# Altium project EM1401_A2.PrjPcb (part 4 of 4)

## Sheet FPGA.SchDoc: FPGA (optional fast AFE)
size B; Date: Not shown in title block; ApprovedBy: Not shown in title block; CheckedBy: Not shown in title block; Author: Not shown in title block; CompanyName: Not shown in title block; DrawnBy: Not shown in title block; Engineer: Not shown in title block; Organization: Not shown in title block; Address1: Not shown in title block; Address2: Not shown in title block; Address3: Not shown in title block; Address4: Not shown in title block; DocumentNumber: 1; Revision: Use project parameter SCH_Rev; SheetNumber: 3; SheetTotal: 14; PageSetup: Record=PageOptions|CenterHorizontal=True|CenterVertical=True|PrintScale=1.00|XCorrection=1.00|YCorrection=1.00|PrintKind=0|BorderSize=5000000|LeftOffset=0|BottomOffset=0|Orientation=2|PaperLength=1000|PaperWidth=1000|Scale=100|PaperSource=15|PrintQuality=600|MediaType=1|DitherType=10|PaperKind=Letter|PrintScaleMode=1
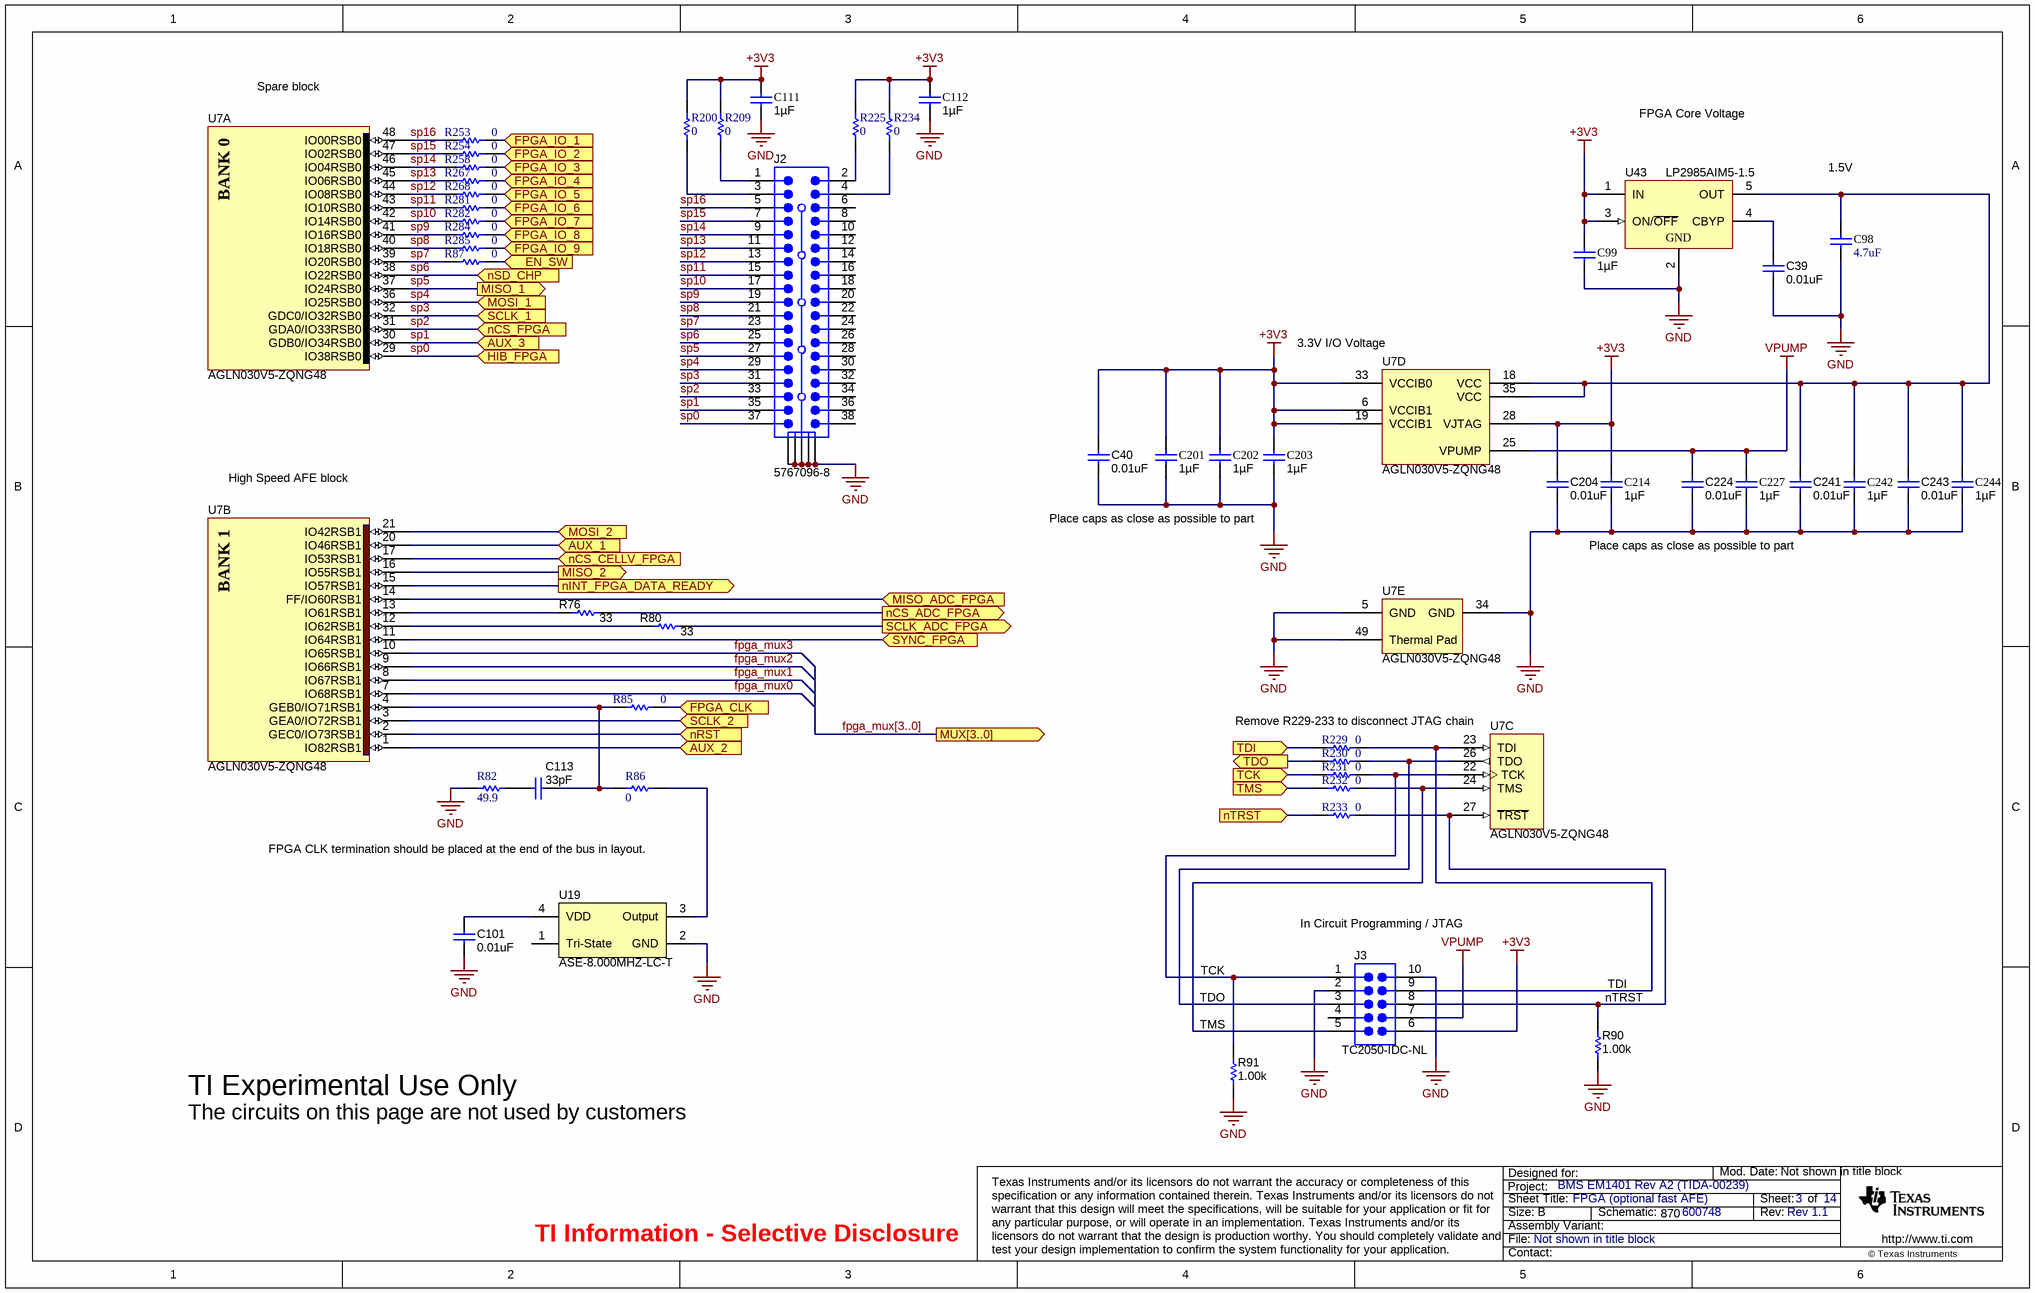
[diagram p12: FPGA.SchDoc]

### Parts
C39  value 0.01uF  [0603L]  (hidden comment: GRM188R71C103KA01D)
C40  value 0.01uF  [0603L]  (hidden comment: GRM188R71C103KA01D)
C98  value 4.7uF  [0805_HV]  (hidden comment: C0805C475K8PACTU)
C99  ValueDisplayed: 1µF  [0603L]  (hidden comment: C1608X7R1C105K)
C101  value 0.01uF  [0603L]  (hidden comment: GRM188R71C103KA01D)
C111  ValueDisplayed: 1µF  [0603L]  (hidden comment: C1608X7R1C105K)
C112  ValueDisplayed: 1µF  [0603L]  (hidden comment: C1608X7R1C105K)
C113  value 33pF  [0603L]  (hidden comment: C1608C0G1H330J)
C201  ValueDisplayed: 1µF  [0603L]  (hidden comment: C1608X7R1C105K)
C202  ValueDisplayed: 1µF  [0603L]  (hidden comment: C1608X7R1C105K)
C203  ValueDisplayed: 1µF  [0603L]  (hidden comment: C1608X7R1C105K)
C204  value 0.01uF  [0603L]  (hidden comment: GRM188R71C103KA01D)
C214  ValueDisplayed: 1µF  [0603L]  (hidden comment: C1608X7R1C105K)
C224  value 0.01uF  [0603L]  (hidden comment: GRM188R71C103KA01D)
C227  ValueDisplayed: 1µF  [0603L]  (hidden comment: C1608X7R1C105K)
C241  value 0.01uF  [0603L]  (hidden comment: GRM188R71C103KA01D)
C242  ValueDisplayed: 1µF  [0603L]  (hidden comment: C1608X7R1C105K)
C243  value 0.01uF  [0603L]  (hidden comment: GRM188R71C103KA01D)
C244  ValueDisplayed: 1µF  [0603L]  (hidden comment: C1608X7R1C105K)
J2  5767096-8  [5767096-8]
J3  TC2050-IDC-NL  [TC2050-IDC-NL-10]
R76  value 33  [0603L]  (hidden comment: CRCW060333R0JNEA)
R80  value 33  [0603L]  (hidden comment: CRCW060333R0JNEA)
R82  value 49.9  [0603L]  (hidden comment: CRCW060349R9FKEA)
R85  value 0  [0603L]  (hidden comment: CRCW06030000Z0EA)
R86  value 0  [0603L]  (hidden comment: CRCW06030000Z0EA)
R87  value 0  [0603L]  (hidden comment: CRCW06030000Z0EA)
R90  value 1.00k  [0402]  (hidden comment: CRCW04021K00FKED)
R91  value 1.00k  [0402]  (hidden comment: CRCW04021K00FKED)
R200  value 0  [0603L]  (hidden comment: CRCW06030000Z0EA)
R209  value 0  [0603L]  (hidden comment: CRCW06030000Z0EA)
R225  value 0  [0603L]  (hidden comment: CRCW06030000Z0EA)
R229  value 0  [0603L]  (hidden comment: CRCW06030000Z0EA)
R230  value 0  [0603L]  (hidden comment: CRCW06030000Z0EA)
R231  value 0  [0603L]  (hidden comment: CRCW06030000Z0EA)
R232  value 0  [0603L]  (hidden comment: CRCW06030000Z0EA)
R233  value 0  [0603L]  (hidden comment: CRCW06030000Z0EA)
R234  value 0  [0603L]  (hidden comment: CRCW06030000Z0EA)
R253  value 0  [0603L]  (hidden comment: CRCW06030000Z0EA)
R254  value 0  [0603L]  (hidden comment: CRCW06030000Z0EA)
R258  value 0  [0603L]  (hidden comment: CRCW06030000Z0EA)
R267  value 0  [0603L]  (hidden comment: CRCW06030000Z0EA)
R268  value 0  [0603L]  (hidden comment: CRCW06030000Z0EA)
R281  value 0  [0603L]  (hidden comment: CRCW06030000Z0EA)
R282  value 0  [0603L]  (hidden comment: CRCW06030000Z0EA)
R284  value 0  [0603L]  (hidden comment: CRCW06030000Z0EA)
R285  value 0  [0603L]  (hidden comment: CRCW06030000Z0EA)
U7  AGLN030V5-ZQNG48  [QN48_N]  (parts A,B,C,D,E of 5)
U19  ASE-8.000MHZ-LC-T  [ASE-xxxMHz-x-x-x]
U43  LP2985AIM5-1.5  [MF05A_N]

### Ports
AUX_1 (in), AUX_2 (in), AUX_3 (in), EN_SW (in), FPGA_CLK (in), FPGA_IO_1 (in), FPGA_IO_2 (in), FPGA_IO_3 (in), FPGA_IO_4 (in), FPGA_IO_5 (in), FPGA_IO_6 (in), FPGA_IO_7 (in), FPGA_IO_8 (in), FPGA_IO_9 (in), HIB_FPGA (in), MISO_1 (out), MISO_2 (out), MISO_ADC_FPGA (in), MOSI_1 (in), MOSI_2 (in), MUX[3..0] (out), nCS_ADC_FPGA (out), nCS_CELLV_FPGA (in), nCS_FPGA (in), nINT_FPGA_DATA_READY (out), nRST (in), nSD_CHP (in), nTRST (in), SCLK_1 (in), SCLK_2 (in), SCLK_ADC_FPGA (out), SYNC_FPGA (in), TCK (in), TDI (in), TDO (out), TMS (in)

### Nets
+3V3: C40.2 C99.2 C111.2 C112.2 C201.2 C202.2 C203.2 C204.2 C214.2 J3.6 R200.1 R209.1 R225.1 R234.1 U7.6(VCCIB1) U7.19(VCCIB1) U7.28(VJTAG) U7.33(VCCIB0) U43.1(IN) U43.3(ON/~{OFF})
GND: C39.1 C40.1 C98.2 C99.1 C101.1 C111.1 C112.1 C201.1 C202.1 C203.1 C204.1 C214.1 C224.1 C227.1 C241.1 C242.1 C243.1 C244.1 J2.39 J2.40 J2.41 J2.42 J2.43 J3.2 J3.10 R82.2 R90.1 R91.1 U7.5(GND) U7.34(GND) U7.49(Thermal_Pad) U19.2(GND) U43.2(GND)  [project net BAT0]
VPUMP: C224.2 C227.2 J3.7 U7.25(VPUMP)
EN_SW_: R87.2 ; port EN_SW
FAULT_INT_BOT_: R267.2 ; port FPGA_IO_4
FAULT_INT_TOP_: R258.2 ; port FPGA_IO_3
FPGA_CLK_: R85.2 ; port FPGA_CLK
FPGA_MUX0: U7.7(IO68RSB1)
FPGA_MUX1: U7.8(IO67RSB1)
FPGA_MUX2: U7.9(IO66RSB1)
FPGA_MUX3: U7.10(IO65RSB1)
JTAG_TDO: R230.1 ; port TDO
JTCK/SWCLK: R231.1 ; port TCK
JTDO/TRACESWO: R229.1 ; port TDI
JTMS/SWDIO: R232.1 ; port TMS
MISO_2_: U7.16(IO55RSB1) ; port MISO_2
MISO_FPGA_: U7.14(FF/IO60RSB1) ; port MISO_ADC_FPGA
MOSI_2_: U7.21(IO42RSB1) ; port MOSI_2
MUX0_: U7.20(IO46RSB1) ; port AUX_1
MUX1_: U7.1(IO82RSB1) ; port AUX_2
MUX3_: U7.15(IO57RSB1) ; port nINT_FPGA_DATA_READY
nCS_ADC_FPGA_: R76.2 ; port nCS_ADC_FPGA
nCS_AFE_: R285.2 ; port FPGA_IO_9
nCS_BOTSTACK_: R254.2 ; port FPGA_IO_2
nCS_CELLV_: U7.17(IO53RSB1) ; port nCS_CELLV_FPGA
nCS_TOPSTACK_: R253.2 ; port FPGA_IO_1
nCS_TS_: R284.2 ; port FPGA_IO_8
nRST: U7.2(GEC0/IO73RSB1) ; port nRST
RS_EMB1428_: R282.2 ; port FPGA_IO_7
SCLK_2_: U7.3(GEA0/IO72RSB1) ; port SCLK_2
SCLK_FPGA_: R80.2 ; port SCLK_ADC_FPGA
sp0: J2.37 U7.29(IO38RSB0) ; port HIB_FPGA  [project net HIB_]
sp1: J2.35 U7.30(GDB0/IO34RSB0) ; port AUX_3  [project net MUX2_]
sp2: J2.33 U7.31(GDA0/IO33RSB0) ; port nCS_FPGA  [project net nCS_FPGA_]
sp3: J2.31 U7.32(GDC0/IO32RSB0) ; port SCLK_1  [project net SCLK_1_]
sp4: J2.29 U7.36(IO25RSB0) ; port MOSI_1  [project net MOSI_1_]
sp5: J2.27 U7.37(IO24RSB0) ; port MISO_1  [project net MISO_1_]
sp6: J2.25 U7.38(IO22RSB0) ; port nSD_CHP  [project net nSD_AFE_CHP_]
sp7: J2.23 R87.1 U7.39(IO20RSB0)
sp8: J2.21 R285.1 U7.40(IO18RSB0)
sp9: J2.19 R284.1 U7.41(IO16RSB0)
sp10: J2.17 R282.1 U7.42(IO14RSB0)
sp11: J2.15 R281.1 U7.43(IO10RSB0)
sp12: J2.13 R268.1 U7.44(IO08RSB0)
sp13: J2.11 R267.1 U7.45(IO06RSB0)
sp14: J2.9 R258.1 U7.46(IO04RSB0)
sp15: J2.7 R254.1 U7.47(IO02RSB0)
sp16: J2.5 R253.1 U7.48(IO00RSB0)
SYNC_: U7.11(IO64RSB1) ; port SYNC_FPGA
VREF_BOT_: R281.2 ; port FPGA_IO_6
VREF_TOP_: R268.2 ; port FPGA_IO_5
NetC39_2: C39.2 U43.4(CBYP)
NetC98_1: C98.1 C241.2 C242.2 C243.2 C244.2 U7.18(VCC) U7.35(VCC) U43.5(OUT)
NetC101_2: C101.2 U19.4(VDD)
NetC113_1: C113.1 R82.1
NetC113_2: C113.2 R85.1 R86.2 U7.4(GEB0/IO71RSB1)
NetJ2_1: J2.1 R209.2
NetJ2_2: J2.2 R225.2
NetJ2_3: J2.3 R200.2
NetJ2_4: J2.4 R234.2
NetJ3_1: J3.1 R91.2 R231.2 U7.22(TCK)
NetJ3_3: J3.3 R230.2 U7.26(TDO)
NetJ3_5: J3.5 R232.2 U7.24(TMS)
NetJ3_8: J3.8 R90.2 R233.2 U7.27(~{TRST})
NetJ3_9: J3.9 R229.2 U7.23(TDI)
NetJ7_3: R233.1 ; port nTRST
NetR76_1: R76.1 U7.13(IO61RSB1)
NetR80_1: R80.1 U7.12(IO62RSB1)
NetR86_1: R86.1 U19.3(Output)

Not connected (* = marked no-connect by the designer): J2 6 8 10 12 14 16 18 20 22 24 26 28 30 32 34 36 38; J3 4; U19 1(Tri-State)

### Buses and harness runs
bus fpga_mux[3..0] = port MUX[3..0]

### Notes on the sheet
- Spare block
- FPGA Core Voltage
- 1.5V
- (near U7) 3.3V I/O Voltage
- (near U7) High Speed AFE block
- Place caps as close as possible to part
- Remove R229-233 to disconnect JTAG chain
- FPGA CLK termination should be placed at the end of the bus in layout.
- TCK
- (near J3) In Circuit Programming / JTAG
- TDO
- (near R91) TMS
- (near R90) TDI
- (near R90) nTRST
- TI Experimental Use Only
- The circuits on this page are not used by customers
- TI Information - Selective Disclosure

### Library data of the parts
C39 C40 C101 C204 C224 C241 C243 = GRM188R71C103KA01D: CAP, CERM, 0.01uF, 16V, +/-10%, X7R, 0603; Manufacturer: MuRata; Cap_Case: 0603; Polarized: N; TaMax_C: 125; TaMin_C: -55; Tolerance_%: 10; VDC_V: 16; Cap_F: 0.00000001; CompType: Capacitor; U/M: EA; ValueDisplayed: 0.01µF
C98 = C0805C475K8PACTU: CAP, CERM, 4.7uF, 10V, +/-10%, X5R, 0805; Manufacturer: Kemet; Cap_Case: 0805; ESR_Ohm: 0.004; IRMS_A: 9.89; Polarized: N; TaMax_C: 85; TaMin_C: -55; Tolerance_%: 10; Cap_F: 0.0000047; CompType: Capacitor; Value1: 0.004 ohm; U/M: EA; ValueDisplayed: 4.7µF
C99 C111 C112 C201-C203 C214 C227 C242 C244 = C1608X7R1C105K: CAP, CERM, 1uF, 16V, +/-10%, X7R, 0603; Manufacturer: TDK; Cap_Case: 0603; ESR_Ohm: 0.0057; Polarized: N; TaMax_C: 125; TaMin_C: -55; Tolerance_%: 10; VDC_V: 16; Cap_F: 0.000001; CompType: Capacitor; Value1: 0.0057 ohm; U/M: EA
C113 = C1608C0G1H330J: CAP, CERM, 33pF, 50V, +/-5%, C0G/NP0, 0603; Manufacturer: TDK; Cap_Case: 0603; ESR_Ohm: 0.2649; Polarized: N; TaMax_C: 125; TaMin_C: -55; Tolerance_%: 5; VDC_V: 50; Cap_F: 0.000000000033; CompType: Capacitor; Value1: 0.2649 ohm; U/M: EA
J2 = 5767096-8 (Mictor 38): Mictor Receptacle, SMD 25mil, 19x2, Gold plated, 236 mil above insulator; Manufacturer: Tyco Electronics; U/M: EA
J3 = TC2050-IDC-NL: TC2050 plug of nails cable; Manufacturer: Tag-Connect; SymbolVersion: use current date i.e. 2008-05-20; SymbolCreator: Use LDAP id; CompType: Connector
R76 R80 = CRCW060333R0JNEA: RES, 33 ohm, 5%, 0.1W, 0603; Manufacturer: Vishay-Dale; CompType: Resistor; Value_Code: 33R0; Tolerance_%: 5; Power_W: 0.1; VDC_V: 75; TempCo: 200 ppm/C; EIA_Code: E24; U/M: EA
R82 = CRCW060349R9FKEA: RES, 49.9 ohm, 1%, 0.1W, 0603; Manufacturer: Vishay-Dale; CompType: Resistor; Tolerance_%: 1; VDC_V: 75; Power_W: 0.1; Value_Code: 49R9; EIA_Code: E96; TempCo: 100 ppm/C; U/M: EA
R85-R87 R200 R209 R225 R229-R234 R253 R254 R258 R267 R268 R281 R282 R284 R285 = CRCW06030000Z0EA: RES, 0 ohm, 5%, 0.1W, 0603; Manufacturer: Vishay-Dale; CompType: Resistor; Tolerance_%: 5; VDC_V: 75; Power_W: 0.1; Value_Code: 0000; EIA_Code: E24; TempCo: 200 ppm/C; U/M: EA
R90 R91 = CRCW04021K00FKED: RES, 1.00k ohm, 1%, 0.063W, 0402; Manufacturer: Vishay-Dale; CompType: Resistor; Tolerance_%: 1; VDC_V: 50; Power_W: 0.063; Res_ohm: 1000; Value_Code: 1k00; EIA_Code: E96; U/M: EA; TempCo: 100 ppm/C
U7 = AGL030V2-QN48: IGLOO Low-Power Flash 1.2/1.5V FPGA with Flash*Freeze, 34 User IOs, 30K System Gates, 1Kbit Flash ROM, 48-Pin QFN, Commercial Grade; Manufacturer: Actel
U19 = ASE-8.000MHZ-LC-T: Oscillator, 8.000MHz, 3.3V, SMD; Manufacturer: Abracon; Tolerance_%: +/-50ppm; Frequency: 8000000; Value1: 8MHz; Value2: 7mA
U43 = LP2985AIM5-1.5: Micropower 150 mA Low-Noise Ultra Low-Dropout Regulator, 5-pin SOT-23; Manufacturer: National Semiconductor; PackageTopMarking: LCHA*XTT; PowerWise: N; CompType: LDO IC

## Sheet Revision_History.SchDoc: Revision History
size B; Date: Not shown in title block; ApprovedBy: Not shown in title block; CheckedBy: Not shown in title block; Author: Not shown in title block; CompanyName: Not shown in title block; DrawnBy: Not shown in title block; Engineer: Not shown in title block; Organization: Not shown in title block; Address1: Not shown in title block; Address2: Not shown in title block; Address3: Not shown in title block; Address4: Not shown in title block; DocumentNumber: 1; Revision: Use project parameter SCH_Rev; SheetNumber: 14; SheetTotal: 14; PageSetup: Record=PageOptions|CenterHorizontal=True|CenterVertical=True|PrintScale=1.00|XCorrection=1.00|YCorrection=1.00|PrintKind=0|BorderSize=5000000|LeftOffset=0|BottomOffset=0|Orientation=2|PaperLength=1000|PaperWidth=1000|Scale=100|PaperSource=15|PrintQuality=600|MediaType=1|DitherType=10|PaperKind=Letter|PrintScaleMode=1
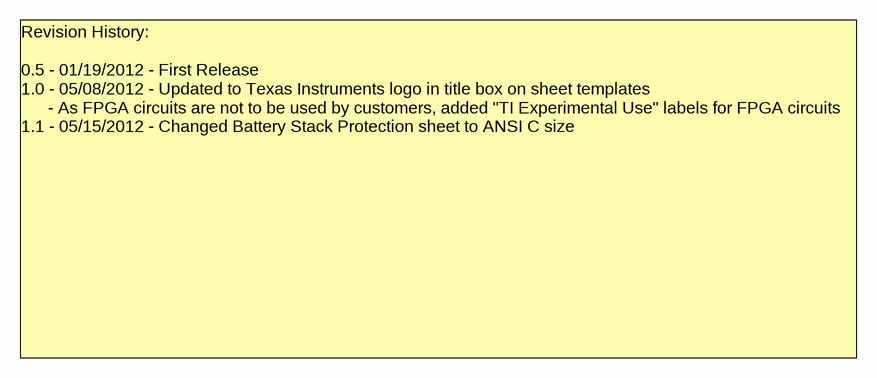
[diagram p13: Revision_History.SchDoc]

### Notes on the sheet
- Revision History:
  0.5 - 01/19/2012 - First Release
  1.0 - 05/08/2012 - Updated to Texas Instruments logo in title box on sheet templates
  - As FPGA circuits are not to be used by customers, added "TI Experimental Use" labels for FPGA circuits
  1.1 - 05/15/2012 - Changed Battery Stack Protection sheet to ANSI C size

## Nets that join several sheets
+3V3: Top_Level (TEST_PORT.8), TOP Half Stack (C120.2 U26.32), BOTTOM Half Stack (C19.2 U6.32), VR (C89.2 L8.2 Q37.3), Cell Sensing (6 pins), uController (15 pins), Communications (C15.2 C80.2 U4.14), Battery Stack Protection (11 pins), TS (R104.1), FPGA (20 pins)
+3V3_LP: Top_Level (TEST_PORT.17), VR (6 pins), uController (27 pins), Communications (R67.1 R151.1 R159.1 U20.14)
+5V5: Top_Level (TEST_PORT.3), VR (10 pins), Cell Sensing (R100.1)
+5V_1: Top_Level (TEST_PORT.9), VR (C87.2 L6.2), Cell Sensing (9 pins), Battery Stack Protection (C71.1 R131.1 U18.28)
+5V_CAN: Top_Level (P3.A8 P3.B8), Communications (5 pins)
+5VD: Top_Level (TEST_PORT.5), TOP Half Stack (C119.2 U26.33), BOTTOM Half Stack (C18.2 U6.33), VR (C20.2 L9.1), Cell Sensing (R271.2), Battery Stack Protection (6 pins), TS (C239.1 U46.3 U46.4)
+12V: Top_Level (TEST_PORT.11), TOP Half Stack (C118.2 C210.2 U26.2 U26.34), TOP_ACB_Converter (9 pins), BOTTOM Half Stack (C17.2 C208.2 U6.2 U6.34), BOTTOM_ACB_Converter (9 pins), VR (8 pins)
+12VF1: Top_Level (TEST_PORT.12), BOTTOM_ACB_Converter (5 pins), VR (C165.1 R218.2 U35.3)
+12VF2: Top_Level (TEST_PORT.14), TOP_ACB_Converter (5 pins), VR (C159.1 R213.2 U33.3)
+VREF: Top_Level (TEST_PORT.13), Cell Sensing (8 pins)
-5V1: Top_Level (TEST_PORT.4), VR (C85.2 L4.2), Cell Sensing (R20.1), Battery Stack Protection (7 pins)
AGND: Cell Sensing (22 pins), Battery Stack Protection (6 pins)
BAT0: Top_Level (5 pins), Engine (D42.2 F15.2 Q47.2 R169.2), TOP Half Stack (9 pins), TOP_ACB_Converter (29 pins), BOTTOM Half Stack (9 pins), BOTTOM_ACB_Converter (29 pins), VR (71 pins), Cell Sensing (12 pins), uController (65 pins), Communications (19 pins), Battery Stack Protection (18 pins), TS (26 pins), FPGA (33 pins)
CAN_GND: Top_Level (6 pins), Communications (13 pins)
GNDF1: Top_Level (TEST_PORT.10), BOTTOM Half Stack (Q4.1 Q4.3 U6.41 U6.43), BOTTOM_ACB_Converter (12 pins), VR (6 pins)
GNDF2: Top_Level (TEST_PORT.16), TOP Half Stack (Q17.1 Q17.3 U26.41 U26.43), TOP_ACB_Converter (12 pins), VR (6 pins)
TIN_P_BOT: Engine (Q46.4 R166.1), TOP Half Stack (R29.2), TOP_ACB_Converter (C132.1 C133.1 C134.1 T3.4), BOTTOM Half Stack (R23.2), BOTTOM_ACB_Converter (C122.1 C123.1 C124.1 T2.4), VR (D10.1 Q12.2 R37.2 R210.2)
AFE_MUX0_: Top_Level (R92.2 R102.2), Cell Sensing (U2.1)
AFE_MUX1_: Top_Level (R97.2 R103.2), Cell Sensing (U2.48)
AFE_MUX2_: Top_Level (R99.2 R141.2), Cell Sensing (U2.47)
AFE_MUX3_: Top_Level (R101.2 R142.2), Cell Sensing (U2.46)
AUX_: Top_Level (TEST_PORT.19), Battery Stack Protection (5 pins)
AUXTH_: Top_Level (TEST_PORT.20), Battery Stack Protection (C79.1 R139.2 R140.1 U18.24)
BAT1: Top_Level (BATTERY.20 D35.2 D39.1), Engine (F14.2), Cell Sensing (R14.1), Battery Stack Protection (R124.1)
BAT2: Top_Level (BATTERY.8 D32.2 D35.1), Engine (F13.2), Cell Sensing (R13.1), Battery Stack Protection (R123.1)
BAT3: Top_Level (BATTERY.7 D29.2 D32.1), Engine (F12.2), Cell Sensing (R12.1), Battery Stack Protection (R122.1)
BAT4: Top_Level (BATTERY.6 D29.1 D43.2), Engine (F11.2), Cell Sensing (R11.1), Battery Stack Protection (R120.1)
BAT5: Top_Level (BATTERY.17 D40.2 D43.1), Engine (F10.2), Cell Sensing (R10.1), Battery Stack Protection (R118.1)
BAT6: Top_Level (BATTERY.16 D37.2 D40.1), Engine (F9.2), Cell Sensing (R9.1), Battery Stack Protection (R116.1)
BAT7: Top_Level (BATTERY.15 D33.2 D37.1), Engine (F8.1), Cell Sensing (R8.1), Battery Stack Protection (R114.1)
BAT8: Top_Level (BATTERY.14 D30.2 D33.1), Engine (F7.2), Cell Sensing (R7.1), Battery Stack Protection (R112.1)
BAT9: Top_Level (BATTERY.5 D30.1 D41.2), Engine (F6.1), Cell Sensing (R6.1), Battery Stack Protection (R111.1)
BAT10: Top_Level (BATTERY.4 D38.2 D41.1), Engine (F5.2), Cell Sensing (R5.1), Battery Stack Protection (R110.1)
BAT11: Top_Level (BATTERY.3 D36.2 D38.1), Engine (F4.2), Cell Sensing (R4.1), Battery Stack Protection (R109.1)
BAT12: Top_Level (BATTERY.2 D34.2 D36.1), Engine (F3.2), Cell Sensing (R3.1), Battery Stack Protection (R108.1)
BAT13: Top_Level (BATTERY.10 D31.2 D34.1), Engine (F2.2), Cell Sensing (R2.1), Battery Stack Protection (R107.1)
BAT14: Top_Level (BATTERY.9 BATTERY.11 R129.1), Engine (D42.1 F1.2), Battery Stack Protection (Q25.2 Q48.2 R89.2 R183.2)
BAT14S_: Top_Level (D31.1 R129.2), Cell Sensing (Q40.2 R1.1 R126.2), Battery Stack Protection (R106.1)
DIR_BOT: BOTTOM Half Stack (U6.25), BOTTOM_ACB_Converter (U27.9)
DIR_RT_BOT: BOTTOM Half Stack (U6.24), BOTTOM_ACB_Converter (U27.10)
DIR_RT_TOP: TOP Half Stack (U26.24), TOP_ACB_Converter (U29.10)
DIR_TOP: TOP Half Stack (U26.25), TOP_ACB_Converter (U29.9)
DONE_BOT: BOTTOM Half Stack (U6.23), BOTTOM_ACB_Converter (U27.11)
DONE_TOP: TOP Half Stack (U26.23), TOP_ACB_Converter (U29.11)
EN_BOT: BOTTOM Half Stack (U6.26), BOTTOM_ACB_Converter (U27.8)
EN_CEXT_BYPASS_: Top_Level (TEST_PORT.7), Battery Stack Protection (Q11.1 R24.1)
EN_Checksum_: Cell Sensing (Q41.1 R137.2), uController (U14.43)
EN_SW_: Engine (Q47.1 R169.1), VR (5 pins), uController (U14.47), FPGA (R87.2)
EN_TOP: TOP Half Stack (U26.26), TOP_ACB_Converter (U29.8)
FAULT_INT_BOT_: BOTTOM Half Stack (U6.31), uController (U14.40), FPGA (R267.2)
FAULT_INT_TOP_: TOP Half Stack (U26.31), uController (U14.37), FPGA (R258.2)
FPGA_CLK_: uController (R88.1), FPGA (R85.2)
FPGA_MUX0: Top_Level (R92.1), FPGA (U7.7)
FPGA_MUX1: Top_Level (R97.1), FPGA (U7.8)
FPGA_MUX2: Top_Level (R99.1), FPGA (U7.9)
FPGA_MUX3: Top_Level (R101.1), FPGA (U7.10)
HEART_: uController (R56.1), Battery Stack Protection (R42.1 U18.2)
HIB_: uController (J4.32 TP1.1 U14.51), FPGA (J2.37 U7.29)
JTAG_TDO: uController (J7.13 R245.2), FPGA (R230.1)
JTCK/SWCLK: uController (J7.9 U14.80), FPGA (R231.1)
JTDO/TRACESWO: uController (R245.1 U14.77), FPGA (R229.1)
JTMS/SWDIO: uController (J7.7 U14.79), FPGA (R232.1)
Manual_Reset_: Top_Level (TEST_PORT.1), uController (SW1.2 U8.4)
MISO_1_: Top_Level (R155.2), TOP Half Stack (U26.29), BOTTOM Half Stack (U6.29), uController (C49.2 U14.30 U44.2), TS (U31.15), FPGA (J2.27 U7.37)
MISO_2_: uController (5 pins), FPGA (U7.16)
MISO_FPGA_: Top_Level (R156.2), FPGA (U7.14)
MOSI_1_: TOP Half Stack (U26.28), BOTTOM Half Stack (U6.28), Cell Sensing (U2.41), uController (C46.2 U14.31 U44.5), TS (U31.14), FPGA (J2.29 U7.36)
MOSI_2_: uController (5 pins), FPGA (U7.21)
MUX0_: Top_Level (R102.1), uController (U14.6), FPGA (U7.20)
MUX1_: Top_Level (R103.1), uController (U14.5), FPGA (U7.1)
MUX2_: Top_Level (R141.1), uController (U14.2), FPGA (J2.35 U7.30)
MUX3_: Top_Level (R142.1), uController (U14.1), FPGA (U7.15)
nCS_ADC_: Top_Level (R143.2 R144.2), Cell Sensing (U3.6)
nCS_ADC_FPGA_: Top_Level (R144.1), FPGA (R76.2)
nCS_AFE_: Cell Sensing (U2.42), uController (U14.90), FPGA (R285.2)
nCS_BOTSTACK_: BOTTOM Half Stack (U6.30), uController (U14.16), FPGA (R254.2)
nCS_CELLV_: Top_Level (R143.1), uController (U14.59), FPGA (U7.17)
nCS_FPGA_: uController (U14.29), FPGA (J2.33 U7.31)
nCS_TOPSTACK_: TOP Half Stack (U26.30), uController (U14.17), FPGA (R253.2)
nCS_TS_: uController (U14.91), TS (U31.1), FPGA (R284.2)
NetC57_2: Top_Level (P3.A2 P3.B2), Communications (C57.2 R40.2 T5.1)
NetC59_1: Top_Level (P3.A1 P3.B1), Communications (C59.1 R41.2 T5.2)
NetC126_1: BOTTOM Half Stack (Q2.5 Q2.6 Q2.7 Q2.8), BOTTOM_ACB_Converter (6 pins)
NetC136_1: TOP Half Stack (Q15.5 Q15.6 Q15.7 Q15.8), TOP_ACB_Converter (6 pins)
NetD4_1: uController (U14.70), Communications (D4.1 P1.2)
NetD5_3: Engine (5 pins), TOP Half Stack (Q14.7 Q14.8)
NetD9_1: uController (U14.71), Communications (D9.1 P1.3)
NetD11_2: Top_Level (D12.1), VR (D11.2 R83.2)
NetF2_1: Engine (F2.1), TOP Half Stack (Q16.7 Q16.8)
NetF3_1: Engine (F3.1), TOP Half Stack (Q18.7 Q18.8)
NetF4_1: Engine (F4.1), TOP Half Stack (Q19.7 Q19.8)
NetF5_1: Engine (F5.1), TOP Half Stack (Q20.7 Q20.8)
NetF6_2: Engine (F6.2), TOP Half Stack (Q21.7 Q21.8)
NetF7_1: Engine (F7.1), TOP Half Stack (Q22.7 Q22.8)
NetF8_2: Engine (F8.2), TOP Half Stack (Q23.7 Q23.8), BOTTOM Half Stack (Q1.7 Q1.8)
NetF9_1: Engine (F9.1), BOTTOM Half Stack (Q3.7 Q3.8)
NetF10_1: Engine (F10.1), BOTTOM Half Stack (Q5.7 Q5.8)
NetF11_1: Engine (F11.1), BOTTOM Half Stack (Q6.7 Q6.8)
NetF12_1: Engine (F12.1), BOTTOM Half Stack (Q7.7 Q7.8)
NetF13_1: Engine (F13.1), BOTTOM Half Stack (Q8.7 Q8.8)
NetF14_1: Engine (F14.1), BOTTOM Half Stack (Q9.7 Q9.8)
NetF15_1: Engine (F15.1), BOTTOM Half Stack (Q10.7 Q10.8)
NetJ7_3: uController (J7.3), FPGA (R233.1)
NetP3_A4: Top_Level (P3.A4 P3.B4), Communications (R163.2)
NetP3_A5: Top_Level (P3.A5 P3.B5), Communications (R160.2 R252.1)
NetQ45_3: uController (U14.50), Communications (Q45.3 R67.2)
NetR27_1: uController (U14.11), Communications (R27.1)
NetR38_1: uController (U14.10), Communications (R38.1)
NetR94_2: VR (R94.2 U13.4), uController (U14.61)
NetU6_20: BOTTOM Half Stack (U6.20), BOTTOM_ACB_Converter (U27.14)
NetU6_21: BOTTOM Half Stack (U6.21), BOTTOM_ACB_Converter (U27.13)
NetU6_22: BOTTOM Half Stack (U6.22), BOTTOM_ACB_Converter (U27.12)
NetU26_20: TOP Half Stack (U26.20), TOP_ACB_Converter (U29.14)
NetU26_21: TOP Half Stack (U26.21), TOP_ACB_Converter (U29.13)
NetU26_22: TOP Half Stack (U26.22), TOP_ACB_Converter (U29.12)
nRS_AFE_: Cell Sensing (U2.39), uController (U14.15)
nRST: uController (J7.15), FPGA (U7.2)
nSD_AFE_: Cell Sensing (U2.40), uController (U14.62)
nSD_AFE_CHP_: Cell Sensing (R50.2 R57.1 U2.38), FPGA (J2.25 U7.38)
RS_EMB1428_: TOP Half Stack (U26.35), BOTTOM Half Stack (U6.35), uController (U14.12), FPGA (R282.2)
SCLK_1_: Top_Level (R157.2), TOP Half Stack (U26.27), BOTTOM Half Stack (U6.27), uController (C61.2 U14.28 U44.6), TS (U31.16), FPGA (J2.31 U7.32)
SCLK_2_: uController (5 pins), FPGA (U7.3)
SCLK_ADC_: Top_Level (R157.1 R158.1), Cell Sensing (U2.43 U3.8)
SCLK_FPGA_: Top_Level (R158.2), FPGA (R80.2)
SDO_ADC_: Top_Level (R155.1 R156.1), Cell Sensing (U2.44 U3.7)
SYNC_: uController (U14.66), Communications (R165.1), FPGA (U7.11)
VREF_BOT_: BOTTOM_ACB_Converter (R54.2), uController (U14.34), FPGA (R281.2)
VREF_TOP_: TOP_ACB_Converter (R53.2), uController (U14.35), FPGA (R268.2)

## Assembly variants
-100A: not fitted C2 C3 C21 C50 C63 C64 C66 C100 C102 C103 C111 C112 C156 C200 C205 C228 C232 C233 C234 C235 C238 C239 C240 CAN_POWER D4 D6 D9 F16 J1 J2 J4 J5 MNT1 MNT2 MNT3 MNT4 MNT5 MNT6 MNT7 MNT8 P1 Q43 R22 R26 R31 R32 R33 R34 R36 R40 R41 R48 R49 R50 R61 R81 R84 R85 R87 R92 R97 R99 R100 R101 R117 R119 R121 R144 R147 R149 R151 R154 R156 R158 R193 R199 R200 R209 R213 R218 R225 R234 R236 R237 R238 R239 R240 R252 R253 R254 R258 R267 R268 R280 R281 R282 R283 R284 R285 R303 R304 RT2 SERIAL_PORT U1 U46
